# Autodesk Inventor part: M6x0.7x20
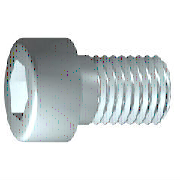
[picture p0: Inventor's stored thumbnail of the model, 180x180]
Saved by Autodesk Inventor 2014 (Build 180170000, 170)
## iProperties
Created: 2009-02
Part Number: M6x0.7x20
Material: 강철, 연강
Description: 6각머리 태핑 나사
Document SubType Name: Modeling
Standard: KS B 1003
Designer: KYOUNG IL JANG
Standards Organization: KS
Language: ko-KR
Size Designation: M 6 x 20
Categories: <MemberInstance><Categories><Category DisplayName="조임쇠" InternalName="e4da775c-781d-43d5-af7c-5136215cf5a6" Mnemonic="FSTN"><Category DisplayName="볼트" InternalN
Density: 7.86 g/cm^3
Mass: 7.48273 g
Surface Area: 7.64101 cm^2
Volume: 0.952001 cm^3
Vendor: CBT Solutions
Appearance: 연마 - 진회색
Company: 한국ATC센터
IsCustomPart: 1
Author: KYOUNG IL JANG
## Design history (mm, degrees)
sketch "스케치1"
  geometry: L1 (-1.333, 0)-(20, 0); L2 (20, 0)-(20, 3); L3 (20, 3)-(2.5, 3); L4 (2.5, 3)-(1.886, 3); L5 (1.886, 3)-(0, 3); L6 (0, 3)-(0, 5); L7 (0, 5)-(-6, 5); L8 (-6, 5)-(-6, 2.887); L9 (-6, 2.887)-(-3, 2.887); L10 (-3, 2.887)-(-1.333, 0); L11 (-11.2, 0)-(25.2, 0) reference; L12 (0, -1)-(0, 6) reference; L13 (2.5, 3)-(0, 3)
  constraints: 22 end point, 6 parallel, 2 collinear, 2 perpendicular, 1 horizontal, 1 point on line
  dimensions: "d1" = 17.5 distance from line of L3.end L2 (= GEL); "d2" = 0.61355 distance of L4.end L3.end (computed from GAL); "d3" = 6 distance between parallel lines of L8 L6 (= KOH); "d4" = 3 distance of L8.end L9.end (= INTI); "d5" = 60 deg angle of L10 L1; "d6" = 6 diameter of L3 L1 (= GD); "d7" = 6 diameter of L5 L1 (= BDM); "d8" = 5.7735 diameter of L9 L1 (= 1.1547 x SW); "d9" = 10 diameter of L7 L1 (= KOD); "d26" = 20 distance between parallel lines of L12 L2 (= NLG)
revolve "본체" sketch "스케치1" stored, may be unused: angle "d10" = 90 deg
sketch "스케치2"
  geometry: L1 (0, -7)-(0, 7) reference; L2 (-7, 0)-(7, 0) reference; L3 (2.887, 0)-(1.443, -2.5); L4 (1.443, -2.5)-(-1.443, -2.5); L5 (-1.443, -2.5)-(-2.887, 0); L6 (-2.887, 0)-(-1.443, 2.5); L7 (-1.443, 2.5)-(1.443, 2.5); L8 (1.443, 2.5)-(2.887, 0); 2 further points
  constraints: 12 end point, 1 coincident, 1 horizontal alignment, 1 point on line, 12 other
extrude "슬롯" join sketch "스케치2" stored distance "d11" = 10; taper "d12" = 0 deg
workplane "Work Plane1"
fillet "Fillet2" dims "d30" = 0.1 (= R)
body "Solid1"
fillet "모깎기1" dims "d17" = 0.6 (= RR)
feature "스레드" dims "d13" = 17.5 (= GEL), "d14" = 0
chamfer "모따기1" distance "d15" = 0.61345 (= -0.5 x SPD + 0.5 x GD); stored, may be unused: second distance "d16" = 0.61345 (= GUL), angle "d27" = 45 deg
other parameters: "GD" = 6 (= NND) [user parameter; used in 2 equation terms], "NLG" = 20 [user parameter; used in 1 equation term], "GEL" = 17.5 [user parameter; used in 2 equation terms], "KOD" = 10 [user parameter; used in 1 equation term], "KOH" = 6 [user parameter; used in 1 equation term], "INTI" = 3 [user parameter; used in 1 equation term], "GAL" = 0.61345 (= 0.61345 x PTC) [user parameter; used in 1 equation term], "GUL" = 0.61345 (= 0.61345 x PTC) [user parameter; used in 1 equation term], "BDM" = 6 (= NND) [user parameter; used in 1 equation term], "SW" = 5 [user parameter; used in 2 equation terms], "RR" = 0.6 [user parameter; used in 1 equation term], "SPD" = 4.7731 (= NND - 1.2269 x PTC) [user parameter; used in 1 equation term], "d19" = 0, "d28" = 0, "d29" = 0, "R" = 0.1 [user parameter; used in 1 equation term], "PHH" = 0.25 [user parameter], "GD1" = 4.7731 (= THREADDIA - 1.2269 x PTC) [user parameter], "THREADDIA" = 6 [user parameter; used in 1 equation term], "FAWI" = 45 deg [user parameter], "PTC" = 1 [user parameter; used in 5 equation terms], "NND" = 6 [user parameter; used in 3 equation terms], "TOA" = 30 deg [user parameter], "E0" = 5.775 (= 1.155 x SW) [user parameter]
